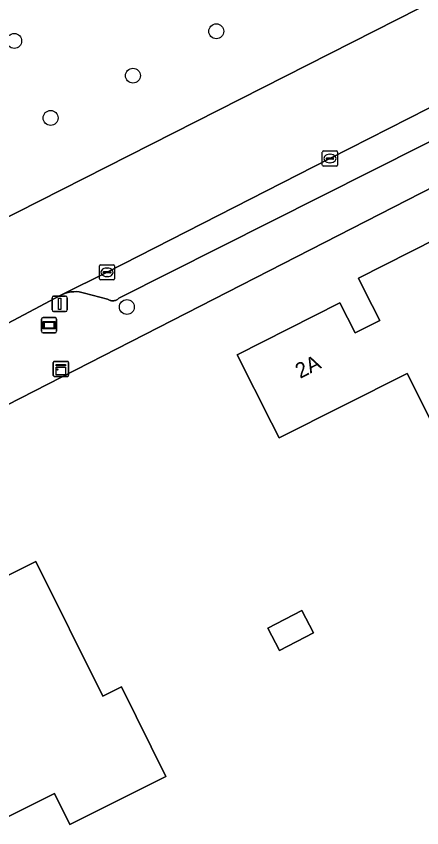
# Model space of a CAD drawing. Extents: x 162722 to 165104, y 384719 to 386284.
# Drawn here: x 163645.7 to 163672.3, y 384930.1 to 384983.4 of the extents above; entities that cross this region are included whole.
import ezdxf

# ---------------------------------------------------------------- set-up
doc = ezdxf.new("R2010")
doc.units = 0
for name, color, linetype in [('IMGEO_Berm_groen', 7, 'Continuous'), ('IMGEO_Boom', 7, 'Continuous'), ('IMGEO_Erf', 7, 'Continuous'), ('IMGEO_Informatiebord', 7, 'Continuous'), ('IMGEO_Kast', 7, 'Continuous'), ('IMGEO_Kolk', 7, 'Continuous'), ('IMGEO_Lichtmast', 7, 'Continuous'), ('IMGEO_Pand', 7, 'Continuous'), ('IMGEO_Pand_nummerreeks', 7, 'Continuous'), ('IMGEO_Parkeervlak_open', 7, 'Continuous'), ('IMGEO_Rijbaan_lokaal_open', 7, 'Continuous'), ('IMGEO_Voetpad_open', 7, 'Continuous')]:
    doc.layers.add(name, color=color, linetype=linetype)

msp = doc.modelspace()

# ---------------------------------------------------------------- linework, layer by layer
at = {"layer": 'IMGEO_Berm_groen'}
msp.add_lwpolyline([(163672.137, 384983.875), (163665.451, 384997.209), (163617.155, 384972.654), (163616.682, 384972.414), (163623.451, 384959.212), (163623.737, 384959.356)], close=True, dxfattribs=at)
at = {"layer": 'IMGEO_Boom'}
for centre in [(163658.832, 384982.388), (163645.556, 384981.755), (163653.357, 384979.476), (163647.946, 384976.703), (163652.958, 384964.297)]:
    msp.add_circle(centre, 0.489, dxfattribs=at)
at = {"layer": 'IMGEO_Erf'}
msp.add_lwpolyline([(163689.085, 384888.134), (163687.084, 384890.632), (163676.468, 384903.753), (163673.969, 384906.848), (163673.753, 384907.134), (163665.55, 384917.268), (163665.421, 384917.261), (163660.75, 384923.114), (163663.751, 384924.681), (163669.399, 384920.052), (163676.37, 384925.254), (163699.363, 384942.796), (163694.404, 384952.9), (163692.876, 384955.959), (163685.319, 384971.004), (163683.732, 384974.099), (163682.29, 384976.876), (163639.563, 384955.061), (163635.539, 384952.364), (163633.451, 384950.624), (163627.464, 384944.399)], dxfattribs=at)
for points in [[(163679.396, 384954.019), (163678.57, 384955.657), (163674.556, 384953.632), (163671.374, 384959.94), (163662.971, 384955.701), (163662.466, 384956.703), (163660.215, 384961.167), (163666.964, 384964.571), (163667.958, 384962.602), (163669.574, 384963.417), (163668.587, 384965.373), (163668.173, 384966.193), (163676.793, 384970.541), (163676.91, 384970.309), (163676.019, 384969.859), (163678.473, 384964.994), (163679.364, 384965.444), (163683.138, 384957.961), (163679.824, 384956.289), (163680.65, 384954.651)], [(163649.213, 384930.337), (163648.201, 384932.371), (163643.97, 384930.266), (163642.165, 384933.895), (163639.816, 384932.727), (163634.505, 384943.403), (163641.429, 384946.847), (163642.236, 384945.225), (163646.981, 384947.585), (163651.375, 384938.752), (163652.6, 384939.361), (163655.527, 384933.478)], [(163662.226, 384943.223), (163664.456, 384944.379), (163665.219, 384942.907), (163662.989, 384941.75)]]:
    msp.add_lwpolyline(points, close=True, dxfattribs=at)
at = {"layer": 'IMGEO_Informatiebord'}
for p, q in [((163647.35, 384962.702), (163647.35, 384963.502)), ((163647.35, 384963.502), (163647.35, 384962.702)), ((163647.45, 384963.602), (163648.24, 384963.602)), ((163648.24, 384963.602), (163647.45, 384963.602)), ((163648.34, 384963.502), (163648.34, 384962.702)), ((163648.34, 384962.702), (163648.34, 384963.502)), ((163648.24, 384962.602), (163647.45, 384962.602)), ((163647.45, 384962.602), (163648.24, 384962.602))]:
    msp.add_line(p, q, dxfattribs=at)
for points in [[(163647.451, 384963.334), (163648.239, 384963.334), (163648.239, 384962.87), (163647.451, 384962.87), (163647.451, 384963.334)], [(163647.516, 384963.269), (163647.516, 384962.935), (163648.174, 384962.935), (163648.174, 384963.269), (163647.516, 384963.269)]]:
    msp.add_lwpolyline(points, dxfattribs=at)
for centre, start, end in [((163647.45, 384963.502), 90, 180), ((163647.45, 384963.502), 90, 180), ((163648.24, 384963.502), 0, 90), ((163648.24, 384963.502), 360, 90), ((163647.45, 384962.702), 180, 270), ((163647.45, 384962.702), 180, 270), ((163648.24, 384962.702), 270, 0), ((163648.24, 384962.702), 270, 0)]:
    msp.add_arc(centre, 0.1, start, end, dxfattribs=at)
at = {"layer": 'IMGEO_Kast'}
for p, q in [((163648.2, 384960.728), (163649.041, 384960.728)), ((163649.041, 384960.728), (163648.2, 384960.728)), ((163648.125, 384959.803), (163648.125, 384960.644)), ((163648.125, 384960.644), (163648.125, 384959.803)), ((163649.125, 384960.653), (163649.125, 384959.812)), ((163649.125, 384959.812), (163649.125, 384960.653)), ((163649.05, 384959.728), (163648.209, 384959.728)), ((163648.209, 384959.728), (163649.05, 384959.728))]:
    msp.add_line(p, q, dxfattribs=at)
for points in [[(163648.32, 384960.518), (163648.92, 384960.518), (163648.92, 384960.433), (163648.32, 384960.433), (163648.32, 384960.518)], [(163648.32, 384960.343), (163648.92, 384960.343), (163648.92, 384959.854), (163648.32, 384959.854), (163648.32, 384960.343)]]:
    msp.add_lwpolyline(points, dxfattribs=at)
msp.add_circle((163648.404, 384960.192), 0.0377, dxfattribs=at)
for centre, start, end in [((163648.203, 384960.65), 92.4484, 184.2845), ((163648.203, 384960.65), 92.4484, 184.2845), ((163649.047, 384960.65), 2.4484, 94.2845), ((163649.047, 384960.65), 2.4484, 94.2845), ((163648.203, 384959.806), 182.4484, 274.2845), ((163648.203, 384959.806), 182.4484, 274.2845), ((163649.047, 384959.806), 272.4484, 4.2845), ((163649.047, 384959.806), 272.4484, 4.2845)]:
    msp.add_arc(centre, 0.0779, start, end, dxfattribs=at)
at = {"layer": 'IMGEO_Kolk'}
for p, q in [((163665.88, 384974.539), (163666.732, 384974.539)), ((163665.805, 384973.613), (163665.805, 384974.465)), ((163666.064, 384974.033), (163666.064, 384974.045)), ((163666.107, 384974.082), (163666.505, 384974.082)), ((163666.293, 384974.319), (163666.318, 384974.319)), ((163666.548, 384974.045), (163666.548, 384974.033)), ((163666.806, 384974.465), (163666.806, 384973.613)), ((163666.732, 384973.539), (163665.88, 384973.539)), ((163666.502, 384973.996), (163666.104, 384973.996)), ((163666.316, 384973.759), (163666.291, 384973.759)), ((163651.153, 384966.146), (163651.153, 384966.998)), ((163651.228, 384967.072), (163652.08, 384967.072)), ((163651.412, 384966.566), (163651.412, 384966.578)), ((163651.455, 384966.615), (163651.853, 384966.615)), ((163651.641, 384966.852), (163651.666, 384966.852)), ((163651.896, 384966.578), (163651.896, 384966.566)), ((163652.154, 384966.998), (163652.154, 384966.146)), ((163652.08, 384966.072), (163651.228, 384966.072)), ((163651.85, 384966.529), (163651.452, 384966.529)), ((163651.664, 384966.292), (163651.639, 384966.292))]:
    msp.add_line(p, q, dxfattribs=at)
for points in [[(163665.88, 384974.539), (163666.732, 384974.539)], [(163665.805, 384973.613), (163665.805, 384974.465)], [(163666.806, 384974.465), (163666.806, 384973.613)], [(163666.732, 384973.539), (163665.88, 384973.539)], [(163651.153, 384966.146), (163651.153, 384966.998)], [(163651.228, 384967.072), (163652.08, 384967.072)], [(163652.154, 384966.998), (163652.154, 384966.146)], [(163652.08, 384966.072), (163651.228, 384966.072)]]:
    msp.add_lwpolyline(points, dxfattribs=at)
for centre, radius, start, end in [((163665.882, 384974.463), 0.0765, 91.552, 178.448), ((163665.882, 384974.463), 0.0765, 91.552, 178.448), ((163666.73, 384974.463), 0.0765, 1.552, 88.448), ((163666.73, 384974.463), 0.0765, 1.552, 88.448), ((163666.104, 384974.042), 0.0403, 85.8775, 175.7526), ((163666.101, 384974.032), 0.0366, 178.938, 274.7102), ((163666.505, 384974.039), 0.043, 264.8664, 352.4533), ((163666.509, 384974.044), 0.0386, 1.7309, 96.639), ((163665.882, 384973.615), 0.0765, 181.552, 268.448), ((163665.882, 384973.615), 0.0765, 181.552, 268.448), ((163666.73, 384973.615), 0.0765, 271.552, 358.448), ((163666.73, 384973.615), 0.0765, 271.552, 358.448), ((163651.23, 384966.996), 0.0765, 91.552, 178.448), ((163651.23, 384966.996), 0.0765, 91.552, 178.448), ((163651.452, 384966.575), 0.0403, 85.8775, 175.7526), ((163651.449, 384966.565), 0.0366, 178.938, 274.7102), ((163651.853, 384966.572), 0.043, 264.8664, 352.4533), ((163651.857, 384966.577), 0.0386, 1.7309, 96.639), ((163652.078, 384966.996), 0.0765, 1.552, 88.448), ((163652.078, 384966.996), 0.0765, 1.552, 88.448), ((163651.23, 384966.148), 0.0765, 181.552, 268.448), ((163651.23, 384966.148), 0.0765, 181.552, 268.448), ((163652.078, 384966.148), 0.0765, 271.552, 358.448), ((163652.078, 384966.148), 0.0765, 271.552, 358.448)]:
    msp.add_arc(centre, radius, start, end, dxfattribs=at)
for centre, major_axis, ratio, start_param, end_param in [((163666.292, 384974.039), (-0.387, 0.002), 0.722429, 4.712389, 7.853982), ((163666.317, 384974.039), (-0.39, 0.002), 0.717154, 1.570796, 4.712389), ((163651.64, 384966.572), (-0.387, 0.002), 0.722429, 4.712389, 7.853982), ((163651.665, 384966.572), (-0.39, 0.002), 0.717154, 1.570796, 4.712389)]:
    msp.add_ellipse(centre, major_axis=major_axis, ratio=ratio, start_param=start_param, end_param=end_param, dxfattribs=at)
at = {"layer": 'IMGEO_Lichtmast'}
for p, q in [((163648.145, 384965.003), (163648.935, 384965.003)), ((163648.935, 384965.003), (163648.145, 384965.003)), ((163648.045, 384964.103), (163648.045, 384964.903)), ((163648.045, 384964.903), (163648.045, 384964.103)), ((163649.035, 384964.903), (163649.035, 384964.103)), ((163649.035, 384964.103), (163649.035, 384964.903)), ((163648.935, 384964.003), (163648.145, 384964.003)), ((163648.145, 384964.003), (163648.935, 384964.003))]:
    msp.add_line(p, q, dxfattribs=at)
msp.add_lwpolyline([(163648.465, 384964.878), (163648.615, 384964.878), (163648.615, 384964.128), (163648.465, 384964.128), (163648.465, 384964.878)], dxfattribs=at)
for centre, start, end in [((163648.145, 384964.903), 90, 180), ((163648.145, 384964.903), 90, 180), ((163648.935, 384964.903), 0, 90), ((163648.935, 384964.903), 360, 90), ((163648.145, 384964.103), 180, 270), ((163648.145, 384964.103), 180, 270), ((163648.935, 384964.103), 270, 0), ((163648.935, 384964.103), 270, 0)]:
    msp.add_arc(centre, 0.1, start, end, dxfattribs=at)
at = {"layer": 'IMGEO_Pand'}
for points in [[(163679.364, 384965.444), (163678.473, 384964.994), (163676.019, 384969.859), (163676.91, 384970.309), (163676.793, 384970.541), (163668.173, 384966.193), (163668.587, 384965.373), (163669.574, 384963.417), (163667.958, 384962.602), (163666.964, 384964.571), (163660.215, 384961.167), (163662.466, 384956.703), (163662.971, 384955.701), (163671.374, 384959.94), (163674.556, 384953.632), (163678.57, 384955.657), (163679.824, 384956.289), (163683.138, 384957.961)], [(163643.97, 384930.266), (163648.201, 384932.371), (163649.213, 384930.337), (163655.527, 384933.478), (163652.6, 384939.361), (163651.375, 384938.752), (163646.981, 384947.585), (163642.236, 384945.225), (163641.429, 384946.847), (163634.505, 384943.403), (163639.816, 384932.727), (163642.165, 384933.895)], [(163662.226, 384943.223), (163662.989, 384941.75), (163665.219, 384942.907), (163664.456, 384944.379)]]:
    msp.add_lwpolyline(points, close=True, dxfattribs=at)
at = {"layer": 'IMGEO_Parkeervlak_open'}
msp.add_lwpolyline([(163677.921, 384979.942), (163666.306, 384974.039), (163651.654, 384966.572), (163648.716, 384965.114), (163648.763, 384965.135), (163648.933, 384965.2), (163649.107, 384965.249), (163649.286, 384965.283), (163649.466, 384965.3), (163649.648, 384965.302), (163649.829, 384965.287), (163650.008, 384965.256), (163650.183, 384965.209), (163651.694, 384964.818), (163651.734, 384964.789), (163651.775, 384964.764), (163651.819, 384964.743), (163651.865, 384964.726), (163651.912, 384964.713), (163651.96, 384964.704), (163652.009, 384964.699), (163652.058, 384964.699), (163652.107, 384964.704), (163652.155, 384964.712), (163652.202, 384964.725), (163652.248, 384964.742), (163652.292, 384964.763), (163652.334, 384964.788), (163652.373, 384964.817), (163652.41, 384964.849), (163652.428, 384964.866), (163675.718, 384976.583)], dxfattribs=at)
at = {"layer": 'IMGEO_Rijbaan_lokaal_open'}
for points in [[(163677.489, 384986.586), (163672.137, 384983.875), (163623.737, 384959.356), (163623.451, 384959.212), (163618.991, 384956.952), (163620.8, 384953.334), (163623.194, 384954.539), (163631.813, 384958.848)], [(163666.306, 384974.039), (163677.921, 384979.942), (163678.259, 384980.084), (163679.377, 384980.48), (163680.527, 384980.775), (163681.095, 384980.851), (163681.787, 384980.887), (163682.479, 384980.861)], [(163632.803, 384957.024), (163643.731, 384962.5), (163648.623, 384965.068), (163648.716, 384965.114), (163651.654, 384966.572), (163666.306, 384974.039)]]:
    msp.add_lwpolyline(points, dxfattribs=at)
at = {"layer": 'IMGEO_Voetpad_open'}
for points in [[(163639.563, 384955.061), (163682.29, 384976.876)], [(163675.718, 384976.583), (163652.428, 384964.866), (163652.41, 384964.849), (163652.373, 384964.817), (163652.334, 384964.788), (163652.292, 384964.763), (163652.248, 384964.742), (163652.202, 384964.725), (163652.155, 384964.712), (163652.107, 384964.704), (163652.058, 384964.699), (163652.009, 384964.699), (163651.96, 384964.704), (163651.912, 384964.713), (163651.865, 384964.726), (163651.819, 384964.743), (163651.775, 384964.764), (163651.734, 384964.789), (163651.694, 384964.818), (163650.183, 384965.209), (163650.008, 384965.256), (163649.829, 384965.287), (163649.648, 384965.302), (163649.466, 384965.3), (163649.286, 384965.283), (163649.107, 384965.249), (163648.933, 384965.2), (163648.763, 384965.135), (163648.716, 384965.114), (163648.623, 384965.068), (163643.731, 384962.5)]]:
    msp.add_lwpolyline(points, dxfattribs=at)

# ---------------------------------------------------------------- texts
at = {"layer": 'IMGEO_Pand_nummerreeks'}
msp.add_text('2A', height=1, rotation=26.7629, dxfattribs=at).set_placement((163664.348, 384959.578))

doc.saveas('drawing.dxf')
